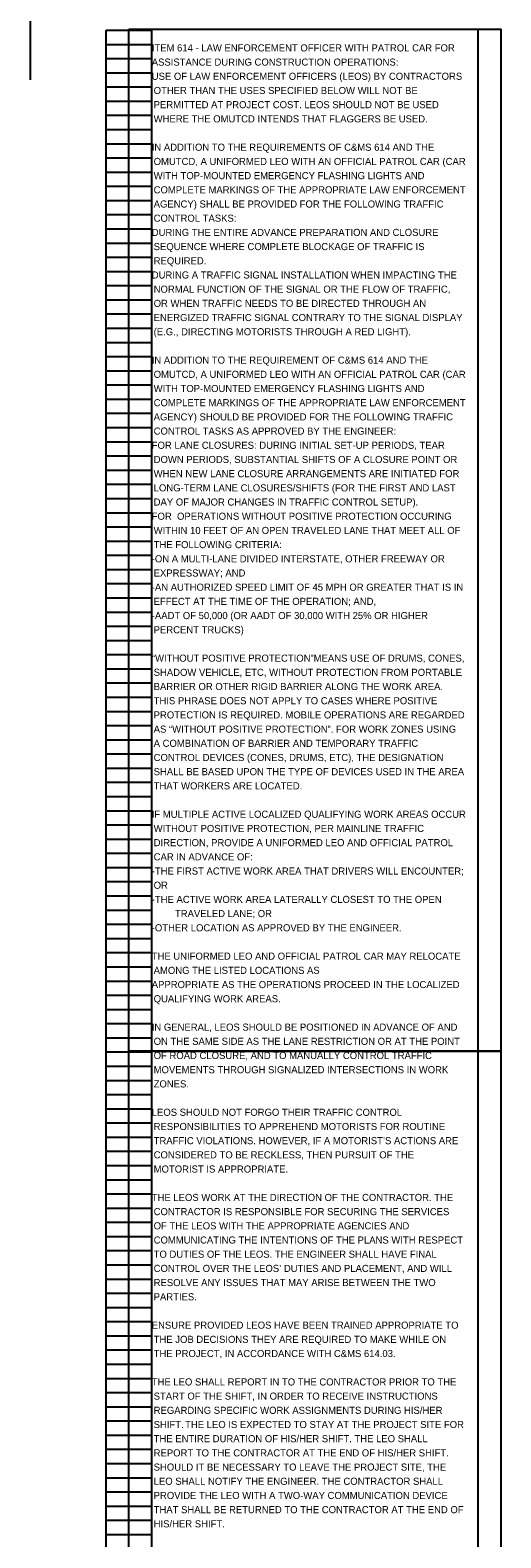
# Model space of a CAD drawing. Extents: x -13 to 29, y -301 to 22.
# Drawn here: x 0 to 9.29, y -109.41 to -79.66 of the extents above; entities that cross this region are included whole.
import ezdxf

# ---------------------------------------------------------------- set-up
doc = ezdxf.new("R2010")
doc.units = 0
doc.layers.add('SC_Scratch1', color=7, linetype='Continuous')
doc.layers.add('SH_Text', color=7, linetype='Continuous')

msp = doc.modelspace()

# ---------------------------------------------------------------- linework, layer by layer
at = {"layer": 'SH_Text'}
for p, q in [((0, -58.64), (0, -80.64)), ((1.5, -79.66), (2.4, -79.66)), ((1.5, -99.82), (1.5, -79.66)), ((2.4, -99.82), (2.4, -79.66)), ((8.84, -99.82), (8.84, -79.66)), ((1.5, -79.94), (2.4, -79.94)), ((1.5, -80.22), (2.4, -80.22)), ((1.5, -80.5), (2.4, -80.5)), ((1.5, -80.78), (2.4, -80.78)), ((1.5, -81.06), (2.4, -81.06)), ((1.5, -81.34), (2.4, -81.34)), ((1.5, -81.62), (2.4, -81.62)), ((1.5, -81.9), (2.4, -81.9)), ((1.5, -82.18), (2.4, -82.18)), ((1.5, -82.46), (2.4, -82.46)), ((1.5, -82.74), (2.4, -82.74)), ((1.5, -83.02), (2.4, -83.02)), ((1.5, -83.3), (2.4, -83.3)), ((1.5, -83.58), (2.4, -83.58)), ((1.5, -83.86), (2.4, -83.86)), ((1.5, -84.14), (2.4, -84.14)), ((1.5, -84.42), (2.4, -84.42)), ((1.5, -84.7), (2.4, -84.7)), ((1.5, -84.98), (2.4, -84.98)), ((1.5, -85.26), (2.4, -85.26)), ((1.5, -85.54), (2.4, -85.54)), ((1.5, -85.82), (2.4, -85.82)), ((1.5, -86.1), (2.4, -86.1)), ((1.5, -86.38), (2.4, -86.38)), ((1.5, -86.66), (2.4, -86.66)), ((1.5, -86.94), (2.4, -86.94)), ((1.5, -87.22), (2.4, -87.22)), ((1.5, -87.5), (2.4, -87.5)), ((1.5, -87.78), (2.4, -87.78)), ((1.5, -88.06), (2.4, -88.06)), ((1.5, -88.34), (2.4, -88.34)), ((1.5, -88.62), (2.4, -88.62)), ((1.5, -88.9), (2.4, -88.9)), ((1.5, -89.18), (2.4, -89.18)), ((1.5, -89.46), (2.4, -89.46)), ((1.5, -89.74), (2.4, -89.74)), ((1.5, -90.02), (2.4, -90.02)), ((1.5, -90.3), (2.4, -90.3)), ((1.5, -90.58), (2.4, -90.58)), ((1.5, -90.86), (2.4, -90.86)), ((1.5, -91.14), (2.4, -91.14)), ((1.5, -91.42), (2.4, -91.42)), ((1.5, -91.7), (2.4, -91.7)), ((1.5, -91.98), (2.4, -91.98)), ((1.5, -92.26), (2.4, -92.26)), ((1.5, -92.54), (2.4, -92.54)), ((1.5, -92.82), (2.4, -92.82)), ((1.5, -93.1), (2.4, -93.1)), ((1.5, -93.38), (2.4, -93.38)), ((1.5, -93.66), (2.4, -93.66)), ((1.5, -93.94), (2.4, -93.94)), ((1.5, -94.22), (2.4, -94.22)), ((1.5, -94.5), (2.4, -94.5)), ((1.5, -94.78), (2.4, -94.78)), ((1.5, -95.06), (2.4, -95.06)), ((1.5, -95.34), (2.4, -95.34)), ((1.5, -95.62), (2.4, -95.62)), ((1.5, -95.9), (2.4, -95.9)), ((1.5, -96.18), (2.4, -96.18)), ((1.5, -96.46), (2.4, -96.46)), ((1.5, -96.74), (2.4, -96.74)), ((1.5, -97.02), (2.4, -97.02)), ((1.5, -97.3), (2.4, -97.3)), ((1.5, -97.58), (2.4, -97.58)), ((1.5, -97.86), (2.4, -97.86)), ((1.5, -98.14), (2.4, -98.14)), ((1.5, -98.42), (2.4, -98.42)), ((1.5, -98.7), (2.4, -98.7)), ((1.5, -98.98), (2.4, -98.98)), ((1.5, -99.26), (2.4, -99.26)), ((1.5, -99.54), (2.4, -99.54)), ((1.5, -99.82), (2.4, -99.82)), ((1.5, -99.82), (2.4, -99.82)), ((1.5, -119.98), (1.5, -99.82)), ((2.4, -119.98), (2.4, -99.82)), ((8.84, -119.98), (8.84, -99.82)), ((1.5, -100.1), (2.4, -100.1)), ((1.5, -100.38), (2.4, -100.38)), ((1.5, -100.66), (2.4, -100.66)), ((1.5, -100.94), (2.4, -100.94)), ((1.5, -101.22), (2.4, -101.22)), ((1.5, -101.5), (2.4, -101.5)), ((1.5, -101.78), (2.4, -101.78)), ((1.5, -102.06), (2.4, -102.06)), ((1.5, -102.34), (2.4, -102.34)), ((1.5, -102.62), (2.4, -102.62)), ((1.5, -102.9), (2.4, -102.9)), ((1.5, -103.18), (2.4, -103.18)), ((1.5, -103.46), (2.4, -103.46)), ((1.5, -103.74), (2.4, -103.74)), ((1.5, -104.02), (2.4, -104.02)), ((1.5, -104.3), (2.4, -104.3)), ((1.5, -104.58), (2.4, -104.58)), ((1.5, -104.86), (2.4, -104.86)), ((1.5, -105.14), (2.4, -105.14)), ((1.5, -105.42), (2.4, -105.42)), ((1.5, -105.7), (2.4, -105.7)), ((1.5, -105.98), (2.4, -105.98)), ((1.5, -106.26), (2.4, -106.26)), ((1.5, -106.54), (2.4, -106.54)), ((1.5, -106.82), (2.4, -106.82)), ((1.5, -107.1), (2.4, -107.1)), ((1.5, -107.38), (2.4, -107.38)), ((1.5, -107.66), (2.4, -107.66)), ((1.5, -107.94), (2.4, -107.94)), ((1.5, -108.22), (2.4, -108.22)), ((1.5, -108.5), (2.4, -108.5)), ((1.5, -108.78), (2.4, -108.78)), ((1.5, -109.06), (2.4, -109.06)), ((1.5, -109.34), (2.4, -109.34))]:
    msp.add_line(p, q, dxfattribs=at)
for points in [[(1.95, -79.643), (9.29, -79.643), (9.29, -99.803), (1.95, -99.803)], [(1.95, -99.803), (9.29, -99.803), (9.29, -119.963), (1.95, -119.963)]]:
    msp.add_lwpolyline(points, close=True, dxfattribs=at)

# ---------------------------------------------------------------- texts
at = {"layer": 'SC_Scratch1'}
for s, p in [('ITEM 614 - LAW ENFORCEMENT OFFICER WITH PATROL CAR FOR ', (2.4, -80.08)), ('ASSISTANCE DURING CONSTRUCTION OPERATIONS:', (2.4, -80.36)), ('USE OF LAW ENFORCEMENT OFFICERS (LEOS) BY CONTRACTORS ', (2.4, -80.64)), ('OTHER THAN THE USES SPECIFIED BELOW WILL NOT BE ', (2.438, -80.92)), ('PERMITTED AT PROJECT COST. LEOS SHOULD NOT BE USED ', (2.438, -81.2)), ('WHERE THE OMUTCD INTENDS THAT FLAGGERS BE USED.', (2.438, -81.48)), ('IN ADDITION TO THE REQUIREMENTS OF C&MS 614 AND THE ', (2.4, -82.04)), ('OMUTCD, A UNIFORMED LEO WITH AN OFFICIAL PATROL CAR (CAR ', (2.438, -82.32)), ('WITH TOP-MOUNTED EMERGENCY FLASHING LIGHTS AND ', (2.438, -82.6)), ('COMPLETE MARKINGS OF THE APPROPRIATE LAW ENFORCEMENT ', (2.438, -82.88)), ('AGENCY) SHALL BE PROVIDED FOR THE FOLLOWING TRAFFIC ', (2.438, -83.16)), ('DURING THE ENTIRE ADVANCE PREPARATION AND CLOSURE ', (2.4, -83.72)), ('CONTROL TASKS:', (2.438, -83.44)), ('SEQUENCE WHERE COMPLETE BLOCKAGE OF TRAFFIC IS ', (2.438, -84)), ('REQUIRED.', (2.438, -84.28)), ('DURING A TRAFFIC SIGNAL INSTALLATION WHEN IMPACTING THE ', (2.4, -84.56)), ('NORMAL FUNCTION OF THE SIGNAL OR THE FLOW OF TRAFFIC, ', (2.438, -84.84)), ('OR WHEN TRAFFIC NEEDS TO BE DIRECTED THROUGH AN ', (2.438, -85.12)), ('ENERGIZED TRAFFIC SIGNAL CONTRARY TO THE SIGNAL DISPLAY ', (2.438, -85.4)), ('(E.G., DIRECTING MOTORISTS THROUGH A RED LIGHT).', (2.438, -85.68)), ('IN ADDITION TO THE REQUIREMENT OF C&MS 614 AND THE ', (2.4, -86.24)), ('OMUTCD, A UNIFORMED LEO WITH AN OFFICIAL PATROL CAR (CAR ', (2.438, -86.52)), ('WITH TOP-MOUNTED EMERGENCY FLASHING LIGHTS AND ', (2.438, -86.8)), ('COMPLETE MARKINGS OF THE APPROPRIATE LAW ENFORCEMENT ', (2.438, -87.08)), ('AGENCY) SHOULD BE PROVIDED FOR THE FOLLOWING TRAFFIC ', (2.438, -87.36)), ('CONTROL TASKS AS APPROVED BY THE ENGINEER:', (2.438, -87.64)), ('FOR LANE CLOSURES: DURING INITIAL SET-UP PERIODS, TEAR ', (2.4, -87.92)), ('WHEN NEW LANE CLOSURE ARRANGEMENTS ARE INITIATED FOR ', (2.438, -88.48)), ('DOWN PERIODS, SUBSTANTIAL SHIFTS OF A CLOSURE POINT OR ', (2.438, -88.2)), ('LONG-TERM LANE CLOSURES/SHIFTS (FOR THE FIRST AND LAST ', (2.438, -88.76)), ('DAY OF MAJOR CHANGES IN TRAFFIC CONTROL SETUP).', (2.438, -89.04)), ('FOR  OPERATIONS WITHOUT POSITIVE PROTECTION OCCURING ', (2.4, -89.32)), ('WITHIN 10 FEET OF AN OPEN TRAVELED LANE THAT MEET ALL OF ', (2.438, -89.6)), ('THE FOLLOWING CRITERIA:', (2.438, -89.88)), ('-ON A MULTI-LANE DIVIDED INTERSTATE, OTHER FREEWAY OR ', (2.4, -90.16)), ('EXPRESSWAY; AND', (2.438, -90.44)), ('-AN AUTHORIZED SPEED LIMIT OF 45 MPH OR GREATER THAT IS IN ', (2.4, -90.72)), ('EFFECT AT THE TIME OF THE OPERATION; AND,', (2.438, -91)), ('-AADT OF 50,000 (OR AADT OF 30,000 WITH 25% OR HIGHER ', (2.4, -91.28)), ('PERCENT TRUCKS)', (2.438, -91.56)), ('“', (2.4, -92.12)), ('WITHOUT POSITIVE PROTECTION”MEANS USE OF DRUMS, CONES, ', (2.465, -92.12)), ('SHADOW VEHICLE, ETC, WITHOUT PROTECTION FROM PORTABLE ', (2.438, -92.4)), ('BARRIER OR OTHER RIGID BARRIER ALONG THE WORK AREA. ', (2.438, -92.68)), ('THIS PHRASE DOES NOT APPLY TO CASES WHERE POSITIVE ', (2.438, -92.96)), ('PROTECTION IS REQUIRED. MOBILE OPERATIONS ARE REGARDED ', (2.438, -93.24)), ('AS “WITHOUT POSITIVE PROTECTION”. FOR WORK ZONES USING ', (2.438, -93.52)), ('A COMBINATION OF BARRIER AND TEMPORARY TRAFFIC ', (2.438, -93.8)), ('CONTROL DEVICES (CONES, DRUMS, ETC), THE DESIGNATION ', (2.438, -94.08)), ('SHALL BE BASED UPON THE TYPE OF DEVICES USED IN THE AREA ', (2.438, -94.36)), ('THAT WORKERS ARE LOCATED.', (2.438, -94.64)), ('IF MULTIPLE ACTIVE LOCALIZED QUALIFYING WORK AREAS OCCUR ', (2.4, -95.2)), ('WITHOUT POSITIVE PROTECTION, PER MAINLINE TRAFFIC ', (2.438, -95.48)), ('DIRECTION, PROVIDE A UNIFORMED LEO AND OFFICIAL PATROL ', (2.438, -95.76)), ('CAR IN ADVANCE OF: ', (2.438, -96.04)), ('-THE FIRST ACTIVE WORK AREA THAT DRIVERS WILL ENCOUNTER; ', (2.4, -96.32)), ('OR', (2.438, -96.6)), ('-THE ACTIVE WORK AREA LATERALLY CLOSEST TO THE OPEN ', (2.4, -96.88)), ('TRAVELED LANE; OR', (2.858, -97.16)), ('-OTHER LOCATION AS APPROVED BY THE ENGINEER.', (2.4, -97.44)), ('THE UNIFORMED LEO AND OFFICIAL PATROL CAR MAY RELOCATE ', (2.4, -98)), ('AMONG THE LISTED LOCATIONS AS', (2.438, -98.28)), ('APPROPRIATE AS THE OPERATIONS PROCEED IN THE LOCALIZED ', (2.4, -98.56)), ('QUALIFYING WORK AREAS.', (2.438, -98.84)), ('IN GENERAL, LEOS SHOULD BE POSITIONED IN ADVANCE OF AND ', (2.4, -99.4)), ('ON THE SAME SIDE AS THE LANE RESTRICTION OR AT THE POINT ', (2.438, -99.68)), ('OF ROAD CLOSURE, AND TO MANUALLY CONTROL TRAFFIC ', (2.438, -99.96)), ('MOVEMENTS THROUGH SIGNALIZED INTERSECTIONS IN WORK ', (2.438, -100.24)), ('ZONES.', (2.438, -100.52)), ('LEOS SHOULD NOT FORGO THEIR TRAFFIC CONTROL ', (2.4, -101.08)), ('RESPONSIBILITIES TO APPREHEND MOTORISTS FOR ROUTINE ', (2.438, -101.36)), ('TRAFFIC VIOLATIONS. HOWEVER, IF A MOTORIST’S ACTIONS ARE ', (2.438, -101.64)), ('CONSIDERED TO BE RECKLESS, THEN PURSUIT OF THE ', (2.438, -101.92)), ('MOTORIST IS APPROPRIATE.', (2.438, -102.2)), ('THE LEOS WORK AT THE DIRECTION OF THE CONTRACTOR. THE ', (2.4, -102.76)), ('CONTRACTOR IS RESPONSIBLE FOR SECURING THE SERVICES ', (2.438, -103.04)), ('OF THE LEOS WITH THE APPROPRIATE AGENCIES AND ', (2.438, -103.32)), ('COMMUNICATING THE INTENTIONS OF THE PLANS WITH RESPECT ', (2.438, -103.6)), ('TO DUTIES OF THE LEOS. THE ENGINEER SHALL HAVE FINAL ', (2.438, -103.88)), ('CONTROL OVER THE LEOS’ DUTIES AND PLACEMENT, AND WILL ', (2.438, -104.16)), ('RESOLVE ANY ISSUES THAT MAY ARISE BETWEEN THE TWO ', (2.438, -104.44)), ('PARTIES.', (2.438, -104.72)), ('ENSURE PROVIDED LEOS HAVE BEEN TRAINED APPROPRIATE TO ', (2.4, -105.28)), ('THE JOB DECISIONS THEY ARE REQUIRED TO MAKE WHILE ON ', (2.438, -105.56)), ('THE PROJECT, IN ACCORDANCE WITH C&MS 614.03.', (2.438, -105.84)), ('THE LEO SHALL REPORT IN TO THE CONTRACTOR PRIOR TO THE ', (2.4, -106.4)), ('START OF THE SHIFT, IN ORDER TO RECEIVE INSTRUCTIONS ', (2.438, -106.68)), ('REGARDING SPECIFIC WORK ASSIGNMENTS DURING HIS/HER ', (2.438, -106.96)), ('THE ENTIRE DURATION OF HIS/HER SHIFT. THE LEO SHALL ', (2.438, -107.52)), ('SHIFT.', (2.438, -107.24)), ('THE LEO IS EXPECTED TO STAY AT THE PROJECT SITE FOR ', (3.058, -107.24)), ('REPORT TO THE CONTRACTOR AT THE END OF HIS/HER SHIFT. ', (2.438, -107.8)), ('SHOULD IT BE NECESSARY TO LEAVE THE PROJECT SITE, THE ', (2.438, -108.08)), ('LEO SHALL NOTIFY THE ENGINEER. THE CONTRACTOR SHALL ', (2.438, -108.36)), ('PROVIDE THE LEO WITH A TWO-WAY COMMUNICATION DEVICE ', (2.438, -108.64)), ('THAT SHALL BE RETURNED TO THE CONTRACTOR AT THE END OF ', (2.438, -108.92)), ('HIS/HER SHIFT.', (2.438, -109.2))]:
    msp.add_text(s, height=0.14, dxfattribs=at).set_placement(p)

doc.saveas('drawing.dxf')
